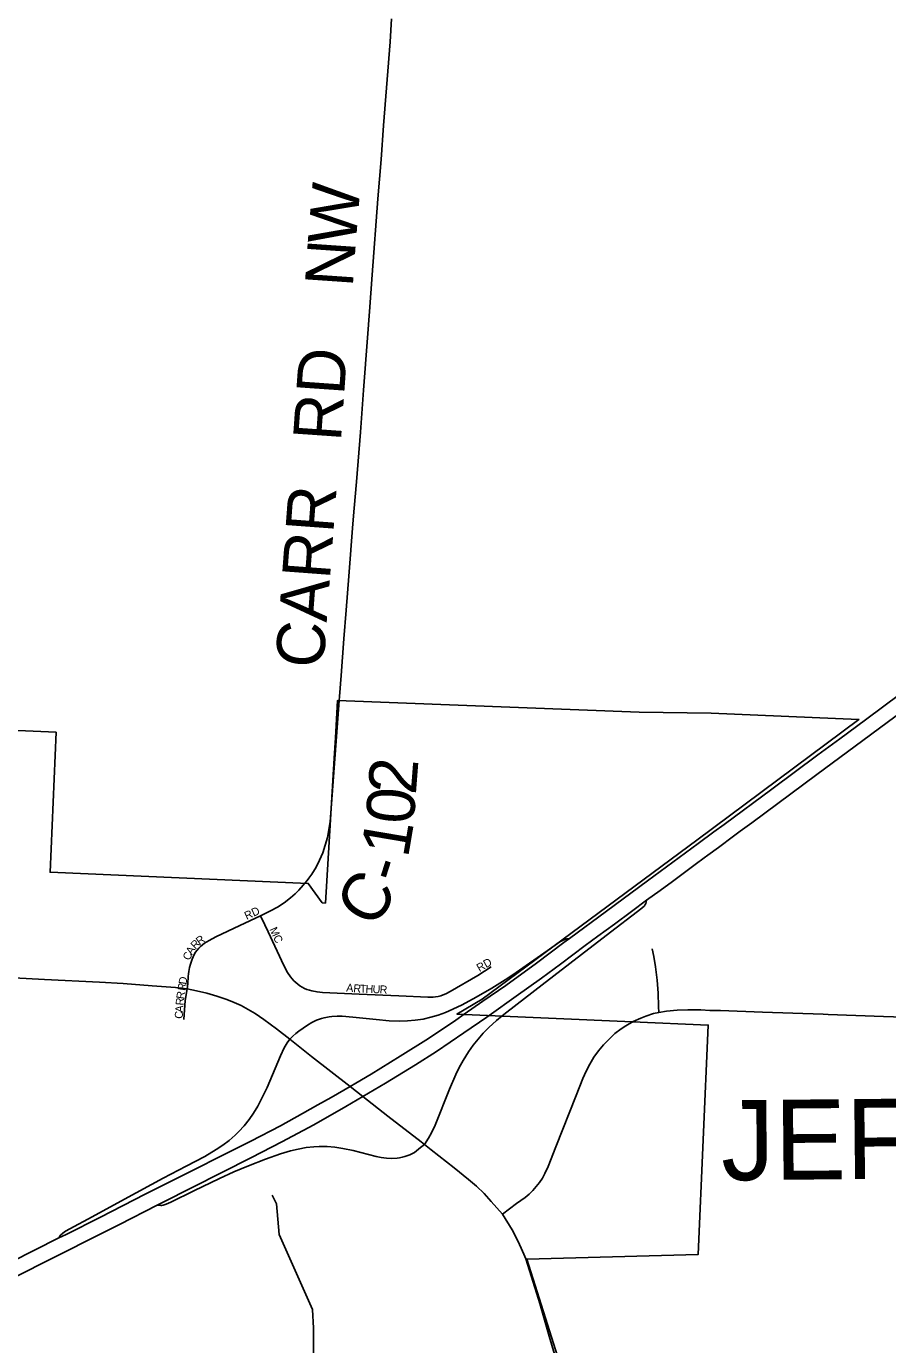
# Model space of a CAD drawing. Extents: x -51392 to 1635000, y 156707 to 696232.
# Drawn here: x 108334 to 113714, y 526284 to 534520 of the extents above; entities that cross this region are included whole.
import ezdxf

# ---------------------------------------------------------------- set-up
doc = ezdxf.new("R2010")
doc.units = 0
for name, color, linetype in [('GM_X_City_Street', 7, 'Continuous'), ('GM_X_City_Street_Text', 7, 'Continuous'), ('GM_X_Corporation', 7, 'Continuous'), ('GM_X_Corporation_Text', 7, 'Continuous'), ('GM_X_County_Road', 7, 'Continuous'), ('GM_X_County_Road_Text', 7, 'Continuous'), ('GM_X_Interchange_Ramps', 7, 'Continuous'), ('GM_X_Interstate_Route', 7, 'Continuous'), ('GM_X_Minor_River', 7, 'Continuous'), ('GM_X_State_Route', 7, 'Continuous')]:
    doc.layers.add(name, color=color, linetype=linetype)

msp = doc.modelspace()

# ---------------------------------------------------------------- linework, layer by layer
at = {"layer": 'GM_X_City_Street'}
for points in [[(109796.2, 528963.5), (109859.7, 528993.7), (109903.1, 529017.8), (109944.6, 529045), (109983.8, 529075.5), (110012.4, 529101.2), (110035.6, 529123.5), (110063.1, 529153.8), (110074, 529167.2)], [(109338.5, 528507.1), (109342, 528537.7), (109344.8, 528583.2), (109346.2, 528600.3), (109348.5, 528614.3), (109353.4, 528639.8), (109359.1, 528661.7), (109369.3, 528692.4), (109382.9, 528721.7), (109390.9, 528735.6), (109400, 528748.8), (109410.2, 528761), (109421.6, 528772.2), (109433.9, 528782.3), (109447.1, 528791.7), (109474.8, 528808.7), (109518.1, 528831.7), (109666.6, 528901.8), (109796.2, 528963.5)], [(109796.2, 528963.5), (109823.3, 528907.1), (109844.7, 528862.6), (109942.7, 528653.8), (109964.9, 528609.7), (109982.9, 528582.1), (109993.1, 528569.2), (110004.3, 528557.2), (110016.4, 528546), (110029.2, 528535.7), (110042.7, 528526.2), (110056.8, 528517.6), (110071.4, 528510), (110086.5, 528503.5), (110102, 528497.9), (110117.8, 528493.5), (110150.2, 528487.4), (110183, 528484.1), (110413.4, 528474.6), (110660.2, 528462.9), (110841.2, 528454.9), (110874.1, 528455.2), (110890.5, 528456.8), (110906.7, 528459.5), (110922.6, 528463.6), (110938.1, 528469.1), (110953.1, 528475.7), (110982.2, 528491.2), (111153.2, 528590.5), (111236.8, 528643.7)], [(109316.6, 528314.5), (109325.8, 528433.5), (109338.5, 528507.1)]]:
    msp.add_lwpolyline(points, dxfattribs=at)
at = {"layer": 'GM_X_Corporation'}
msp.add_lwpolyline([(105749, 530231.1), (108519.5, 530109.9), (108481.5, 529235.6), (110094.7, 529165.3), (110181.6, 529044.7), (110201.6, 529043.2), (110257.4, 529947.8), (110264.1, 530074.3), (110278.2, 530308.8), (112162.5, 530234.9), (112611.8, 530229.7), (113535.2, 530190.4), (112522.2, 529436.4), (111180.5, 528442.3), (111022.9, 528349.3), (112120.7, 528301.5), (112593.6, 528280.9), (112531.2, 526847.7), (111459.3, 526818.9), (111819.6, 525679.5)], dxfattribs=at)
at = {"layer": 'GM_X_County_Road'}
for points in [[(110288.2, 530309.3), (110290.4, 530333), (110300.1, 530463.9), (110316.5, 530693), (110331.3, 530872.9), (110348, 531085.6), (110373.8, 531412.8), (110382.3, 531510.9), (110395.8, 531674.4), (110420, 531985.3), (110439.8, 532247.2), (110464.5, 532574.4), (110477.5, 532738), (110494.1, 532967.2), (110529.9, 533441.8), (110549.1, 533687.2), (110564.8, 533899.9), (110605.7, 534423.5), (110615.7, 534567.7)], [(110074, 529167.2), (110087.7, 529183.9), (110099.1, 529199), (110117.4, 529224.3), (110143.1, 529267.2), (110165.5, 529311.7), (110185, 529357.7), (110201.2, 529404.9), (110214, 529453.1), (110224.1, 529501.9), (110230.6, 529551.3), (110288.2, 530309.3)], [(112284.1, 528359.8), (112283, 528397.4), (112279.9, 528479.7), (112273.5, 528561.9), (112263.9, 528643.8), (112253.4, 528708.9), (112242.9, 528757.2)]]:
    msp.add_lwpolyline(points, dxfattribs=at)
at = {"layer": 'GM_X_Interchange_Ramps'}
for points in [[(110820.5, 527534.2), (110846.2, 527573.9), (110863.9, 527607.6), (110887.9, 527655.5), (110976.6, 527881), (111016, 527971.4), (111037.7, 528015.6), (111061.4, 528058.8), (111096.5, 528114.4), (111125.1, 528154.6), (111155.7, 528193.2), (111188.3, 528230.2), (111222.8, 528265.4), (111271.5, 528309.5), (111305.9, 528337.7), (111335, 528361.7), (111556.4, 528532.4), (111802, 528721.2), (111956.6, 528839.7), (112178.5, 529010.7), (112194.7, 529026.5), (112199.9, 529033.3), (112203.9, 529040.3), (112206.6, 529049.2), (112208.3, 529060.2)], [(111725.7, 528821.7), (111710.9, 528819.2), (111696.6, 528815.5), (111682.5, 528808.8), (111666.5, 528799.7), (111587.1, 528744.2), (111393.2, 528608.9), (111325.2, 528563.6), (111241.8, 528512), (111142.8, 528454.4), (111056.5, 528407.8), (110997.6, 528379.2), (110952.5, 528359.9), (110906.5, 528343), (110859.6, 528329), (110811.8, 528318.1), (110763.3, 528310.8), (110714.4, 528306.9), (110665.4, 528305.9), (110600, 528308), (110518.6, 528314.9), (110372.2, 528330.6), (110307, 528335.3), (110274.2, 528336.2), (110241.5, 528334.7), (110225.3, 528333), (110193.3, 528326.8), (110177.6, 528322.6), (110147, 528311.2), (110117.8, 528296.7), (110089.6, 528279.9), (110035.6, 528243.1), (110017.3, 528227.8), (109997.8, 528210.6), (109978.9, 528191.8)], [(109978.9, 528191.8), (109963.1, 528169), (109945, 528138.5), (109921.6, 528088.6), (109837.6, 527891.4), (109809.7, 527831.7), (109778.9, 527773.4), (109753.2, 527731.1), (109724.9, 527690.5), (109694.2, 527651.8), (109660.9, 527615.3), (109637.4, 527592.2), (109599.8, 527560.1), (109560.4, 527530.4), (109519.4, 527502.7), (109448.6, 527460.4), (109331.9, 527399.4), (109188.3, 527324.4), (108946.3, 527192.9), (108744.3, 527083.4), (108605.1, 527007.8), (108577.9, 526992.7), (108561.1, 526981.4), (108547.3, 526967.9), (108536.5, 526950.5)], [(109151.7, 527155.1), (109173.5, 527153.3), (109180.8, 527154.1), (109189.2, 527155.8), (109207.8, 527161.4), (109235.6, 527173.9), (109380.7, 527245.8), (109539.4, 527323), (109629.3, 527363.9), (109720.4, 527402.2), (109828.1, 527443.4), (109921.5, 527475.5), (109984.6, 527494.6), (110032.5, 527506.3), (110081.2, 527514.9), (110130.2, 527520.7), (110163.1, 527522.5), (110212.5, 527521.7), (110261.6, 527517.3), (110310.5, 527510), (110374.9, 527496.5), (110518.6, 527459.9), (110550.9, 527453.6), (110583.6, 527449.5), (110616.4, 527447.7), (110649.3, 527449.2), (110665.6, 527451.4), (110681.7, 527454.5), (110697.6, 527458.8), (110728.5, 527470.2), (110757.7, 527485.4), (110796.5, 527515.5), (110820.5, 527534.2)]]:
    msp.add_lwpolyline(points, dxfattribs=at)
at = {"layer": 'GM_X_Interstate_Route'}
for points in [[(111224.3, 528340.1), (111394.5, 528460.8), (111551.2, 528574.4), (111670.1, 528661.9), (111825.2, 528777.7), (111904.5, 528835.9), (112007.4, 528912), (112113.8, 528990.4), (112208.3, 529060.2), (112292.6, 529122.2), (112369.4, 529178.3), (112511.6, 529284), (112567, 529325), (112590.8, 529342.5), (112657, 529390.8), (112751.8, 529461.3), (112793.7, 529492.8), (112865.3, 529544.7), (113271.1, 529845.8), (113511.1, 530023.4), (113711.6, 530171.6), (114091.9, 530451.9)], [(108237.5, 526799.5), (108536.5, 526950.5), (108582.3, 526972.8), (108795.9, 527079.5), (109076.3, 527223.5), (109326.5, 527350.1), (109606.3, 527490.6), (109736.4, 527555.4), (109920.4, 527651.1), (110059.3, 527727.3), (110155.1, 527781.7), (110238.5, 527828.8), (110355.9, 527896.7), (110391, 527917), (110488.5, 527973.8), (110669.3, 528086), (110844.8, 528196.5), (111016.7, 528311), (111069.3, 528347.8), (111185, 528429.1), (111329.1, 528528.5), (111520.9, 528667.6), (111692.1, 528796.4), (111725.7, 528821.7), (111958.3, 528992.1), (112213.1, 529181.6), (112530.6, 529415.2), (112629.3, 529487.4), (112693.6, 529534.4), (112989.9, 529754.2), (113277.3, 529969), (113414.9, 530068.4), (113576.6, 530187.6), (113797.3, 530353.1)], [(107621.4, 526382.8), (107804.7, 526475.6), (108123.7, 526637.2), (108463.5, 526808.5), (108840.2, 526998.1), (108914.7, 527035.6), (109151.7, 527155.1), (109184.7, 527171.9), (109740.2, 527453.3), (109929.8, 527551.1), (110129.1, 527658.4), (110329.2, 527771.1), (110436.1, 527833.8), (110577.9, 527917.7), (110765.1, 528032.9), (110894.9, 528116.2), (111066.5, 528231.4), (111209.8, 528329.9), (111224.3, 528340.1)]]:
    msp.add_lwpolyline(points, dxfattribs=at)
at = {"layer": 'GM_X_Minor_River'}
msp.add_lwpolyline([(109869.8, 527218.6), (109896, 527164.6), (109912.8, 526972.4), (110120.7, 526502.7), (110127.1, 526386.6), (110124.9, 525959.9), (110153.7, 525761.8), (110236.5, 525571.9), (110353, 525436.2), (110489.2, 525366.7), (110741.3, 525303.7), (110981.7, 525174.6), (111187.9, 525101.4), (111262.1, 525045.7), (111294.2, 524995.8), (111318.7, 524885.7), (111335.4, 524711.5), (111383.9, 524587.6), (111500.3, 524465.9), (111614.9, 524386)], dxfattribs=at)
at = {"layer": 'GM_X_State_Route'}
for points in [[(109338.5, 528507.1), (109265.8, 528514.7), (109118.6, 528526.7), (108938.8, 528540.7), (108791.4, 528549.5), (108447.5, 528566.2), (108021.9, 528587.5), (107842, 528599.7), (107694.5, 528607.2), (107547.3, 528614.9), (107383.4, 528623), (107219.8, 528630.8), (106990.6, 528643.1), (106695.9, 528657.8), (106514.9, 528667)], [(110041.3, 528142.8), (109978.9, 528191.8), (109895.8, 528257.1), (109817, 528316.3), (109762.5, 528353.2), (109720.2, 528378.7), (109676.5, 528401.9), (109631.6, 528422.6), (109585.6, 528440.7), (109523.2, 528461.8), (109460, 528480), (109395.9, 528495.1), (109338.5, 528507.1)], [(111307.9, 527099.1), (111395.7, 527165.7), (111448.8, 527204.2), (111473.8, 527225), (111497.3, 527247.4), (111519.2, 527271.5), (111539.4, 527297), (111557.2, 527324), (111572.9, 527352.5), (111593.4, 527396.9), (111641.9, 527518.9), (111767.5, 527840.5), (111810.8, 527947.3), (111831.1, 527992.4), (111853.8, 528036.5), (111879.3, 528079.1), (111908.3, 528119.5), (111940.1, 528157.6), (111974.3, 528193.6), (112010.9, 528227.2), (112050.3, 528257.5), (112078, 528275.8), (112123.8, 528302.1), (112172.5, 528324.5), (112203.4, 528336.9), (112251.1, 528351.9), (112284.1, 528359.8), (112332.8, 528367.6), (112398.9, 528373.8), (112465.2, 528376.5), (112548, 528375.3), (112603.7, 528371.9)], [(112603.7, 528371.9), (112671, 528371.2), (112933.3, 528361.6), (113310.6, 528348.4)], [(113310.6, 528348.4), (113343.4, 528347.3), (113687.7, 528334.8), (114064.9, 528321.2)], [(110862.2, 527501.8), (110820.5, 527534.2), (110799.8, 527550.4), (110592.4, 527711), (110436.1, 527833.8), (110355.9, 527896.7), (110114.9, 528084.9), (110041.3, 528142.8)], [(111307.9, 527099.1), (111237.2, 527179), (111192.6, 527227.4), (111145.4, 527273.3), (111096, 527316.7), (111006.8, 527389.2), (110862.2, 527501.8)], [(111453.7, 526819.5), (111441.8, 526850.3), (111433.9, 526868.5), (111406, 526928.2), (111367.5, 527000.9), (111307.9, 527099.1)], [(111533.2, 526567.7), (111453.7, 526819.5)], [(111795.2, 525670.4), (111711, 525957.8), (111656.1, 526147.2), (111600.5, 526336.5), (111541.4, 526541.9), (111533.2, 526567.7)]]:
    msp.add_lwpolyline(points, dxfattribs=at)

# ---------------------------------------------------------------- texts
at = {"layer": 'GM_X_City_Street_Text'}
for s, rotation, p in [('RD', 24.49765, (109709.6, 528937.4)), ('R', 35.73746, (109415.2, 528778.1)), ('M', 294.17002, (109851, 528879.2)), ('C', 295.72812, (109873.2, 528829.7)), ('C', 68.29973, (109354.6, 528681.2)), ('A', 58.52157, (109368.2, 528716)), ('R', 45.88204, (109389.4, 528751.2)), ('RD', 29.895, (111163.9, 528611.9)), ('D', 80.81034, (109333, 528531.5)), ('R', 81.46744, (109318.8, 528440.3)), ('R', 80.83765, (109326.7, 528492.4)), ('A', 354.58217, (110330.2, 528490.8)), ('R', 355.21107, (110374.6, 528486.6)), ('T', 357.53721, (110416.3, 528483.1)), ('H', 358.12191, (110452, 528481.6)), ('U', 358.14442, (110496, 528480.2)), ('R', 358.14372, (110540, 528478.7)), ('R', 84.65155, (109315.2, 528401.6)), ('C', 86.06533, (109309.4, 528318.5)), ('A', 86.05265, (109312.2, 528358))]:
    msp.add_text(s, height=50, rotation=rotation, dxfattribs=at).set_placement(p)
at = {"layer": 'GM_X_Corporation_Text'}
msp.add_text('JEFFERSONVILLE', height=500, rotation=0.53856, dxfattribs=at).set_placement((112675.6, 527310.4))
at = {"layer": 'GM_X_County_Road_Text'}
for s, rotation, p in [('W', 85.35513, (110390.5, 533148.6)), ('N', 86.05322, (110372.4, 532886.2)), ('RD', 85.99978, (110298.2, 531922.6)), ('CARR', 85.75166, (110188.2, 530504.8)), ('2', 85.59774, (110766.4, 529715.1)), ('0', 85.46666, (110751.8, 529530.2)), ('1', 80.36663, (110717.2, 529319)), ('C', 58.28287, (110505.9, 528874.7)), ('-', 72.28621, (110668.8, 529156.8))]:
    msp.add_text(s, height=300, rotation=rotation, dxfattribs=at).set_placement(p)

doc.saveas('drawing.dxf')
